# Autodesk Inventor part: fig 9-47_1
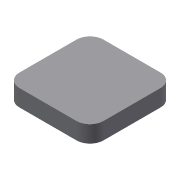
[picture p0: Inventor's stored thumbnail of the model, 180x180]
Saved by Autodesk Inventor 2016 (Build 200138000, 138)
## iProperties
Created: 2013-03
Part Number: fig 9-47_1
Material: Generic
Document SubType Name: Modeling
Designer: CADCIM
Density: 1 g/cm^3
Appearance: Default
Author: CADCIM
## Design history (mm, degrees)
sketch "Sketch1"
  geometry: L1 (-12.5, 12.5)-(12.5, 12.5); L2 (12.5, 12.5)-(12.5, -12.5); L3 (12.5, -12.5)-(-12.5, -12.5); L4 (-12.5, -12.5)-(-12.5, 12.5); 1 further point
  constraints: 8 end point, 2 parallel, 1 horizontal, 1 perpendicular
  dimensions: "d0" = 25 distance of L1.start L1.end; "d2" = 25 distance of L1.end L2.end
extrude "Extrusion1" new body sketch "Sketch1" distance "d3" = 5; taper "d4" = 0 deg
fillet "Fillet1" dims "d5" = 4
body "Solid1"
